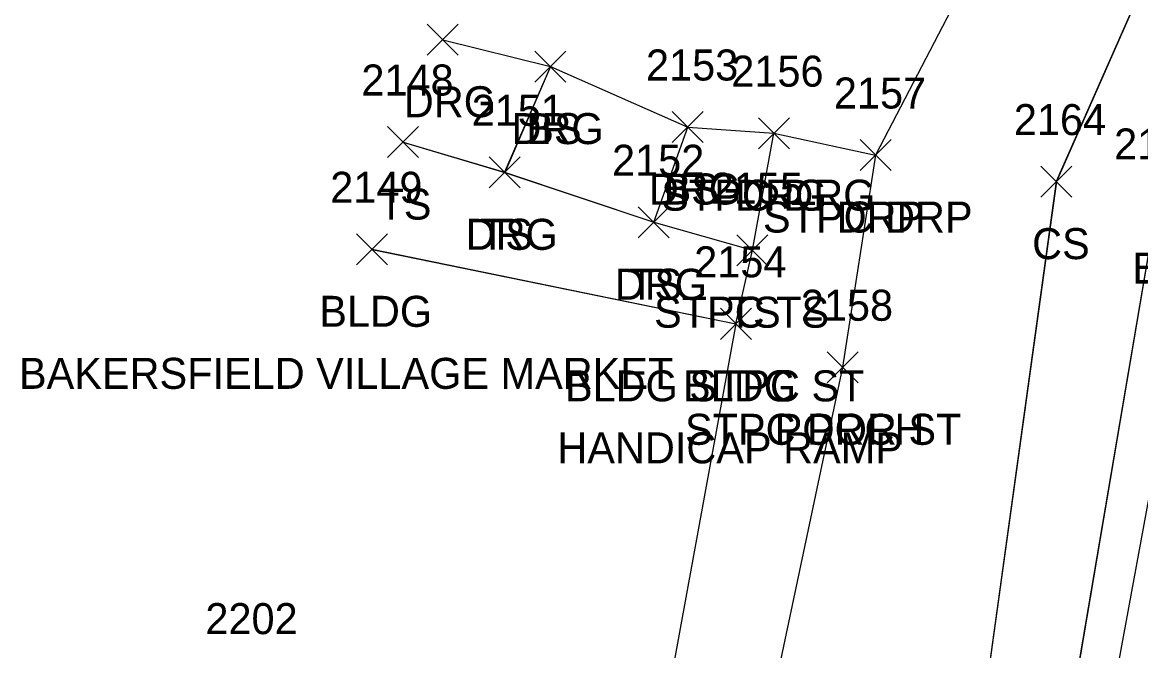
# Model space of a CAD drawing. Extents: x 1554668 to 1563881, y 831386 to 834374.
# Drawn here: x 1562076.1 to 1562148.2, y 832159.9 to 832200.4 of the extents above; entities that cross this region are included whole.
import ezdxf

# ---------------------------------------------------------------- set-up
doc = ezdxf.new("R2010")
doc.units = 0
for name, color, linetype in [('L_A', 7, 'Continuous'), ('L_C', 7, 'Continuous'), ('L_I', 7, 'Continuous'), ('L_TIC', 7, 'Continuous'), ('LBC', 7, 'Continuous'), ('LBF', 7, 'Continuous'), ('LELB', 7, 'Continuous'), ('PET', 7, 'Continuous'), ('R_A', 7, 'Continuous'), ('R_I', 7, 'Continuous'), ('R_TIC', 7, 'Continuous'), ('RDG', 7, 'Continuous'), ('RDP', 7, 'Continuous')]:
    doc.layers.add(name, color=color, linetype=linetype)

msp = doc.modelspace()

# ---------------------------------------------------------------- linework, layer by layer
at = {"layer": 'L_TIC'}
for points in [[(1562109.153, 832196.571), (1562111.153, 832198.571)], [(1562111.153, 832196.571), (1562109.153, 832198.571)], [(1562118.011, 832192.673), (1562120.011, 832194.673)], [(1562120.011, 832192.673), (1562118.011, 832194.673)], [(1562123.569, 832192.276), (1562125.569, 832194.276)], [(1562125.569, 832192.276), (1562123.569, 832194.276)], [(1562099.654, 832191.705), (1562101.654, 832193.705)], [(1562101.654, 832191.705), (1562099.654, 832193.705)], [(1562130.13, 832190.866), (1562132.13, 832192.866)], [(1562132.13, 832190.866), (1562130.13, 832192.866)], [(1562106.199, 832189.752), (1562108.199, 832191.752)], [(1562108.199, 832189.752), (1562106.199, 832191.752)], [(1562141.785, 832189.152), (1562143.785, 832191.152)], [(1562143.785, 832189.152), (1562141.785, 832191.152)], [(1562115.821, 832186.53), (1562117.821, 832188.53)], [(1562117.821, 832186.53), (1562115.821, 832188.53)], [(1562097.651, 832184.786), (1562099.651, 832186.786)], [(1562099.651, 832184.786), (1562097.651, 832186.786)], [(1562122.185, 832184.729), (1562124.185, 832186.729)], [(1562124.185, 832184.729), (1562122.185, 832186.729)], [(1562122.185, 832184.729), (1562124.185, 832186.729)], [(1562124.185, 832184.729), (1562122.185, 832186.729)], [(1562121.12, 832179.979), (1562123.12, 832181.979)], [(1562123.12, 832179.979), (1562121.12, 832181.979)], [(1562121.12, 832179.979), (1562123.12, 832181.979)], [(1562123.12, 832179.979), (1562121.12, 832181.979)], [(1562127.997, 832177.178), (1562129.997, 832179.178)], [(1562129.997, 832177.178), (1562127.997, 832179.178)], [(1562127.997, 832177.178), (1562129.997, 832179.178)], [(1562129.997, 832177.178), (1562127.997, 832179.178)]]:
    msp.add_lwpolyline(points, dxfattribs=at)
at = {"layer": 'LBC'}
for points in [[(1562098.651, 832185.786), (1562122.12, 832180.979), (1562116.884, 832152.384), (1562091.236, 832157.966)], [(1562098.652, 832185.784), (1562122.122, 832180.976)], [(1562098.652, 832185.784), (1562122.122, 832180.976)], [(1562098.652, 832185.784), (1562122.122, 832180.976)]]:
    msp.add_lwpolyline(points, dxfattribs=at)
at = {"layer": 'LBF'}
for points in [[(1562122.12, 832180.979), (1562123.185, 832185.729), (1562124.569, 832193.276), (1562131.13, 832191.866), (1562128.997, 832178.178)], [(1562122.122, 832180.976), (1562123.192, 832185.728), (1562124.571, 832193.274), (1562131.131, 832191.864), (1562129.002, 832178.176)], [(1562122.122, 832180.976), (1562123.192, 832185.728), (1562124.571, 832193.274), (1562131.131, 832191.864), (1562129.002, 832178.176)], [(1562122.122, 832180.976), (1562123.192, 832185.728), (1562124.571, 832193.274), (1562131.131, 832191.864), (1562129.002, 832178.176)], [(1562128.997, 832178.178), (1562123.536, 832152.362)], [(1562129.002, 832178.176), (1562123.54, 832152.361)], [(1562129.002, 832178.176), (1562123.54, 832152.361)], [(1562129.002, 832178.176), (1562123.54, 832152.361)]]:
    msp.add_lwpolyline(points, dxfattribs=at)
at = {"layer": 'LELB'}
for points in [[(1562159.554, 832227.311), (1562154.233, 832216.107), (1562149.254, 832188.579), (1562142.829, 832150.769), (1562138.278, 832124.139), (1562134.77, 832104.225), (1562125.205, 832097.127)], [(1562159.553, 832227.312), (1562154.234, 832216.106), (1562149.258, 832188.577), (1562142.835, 832150.769), (1562138.281, 832124.137), (1562134.773, 832104.223), (1562125.206, 832097.122)], [(1562159.553, 832227.312), (1562154.234, 832216.106), (1562149.258, 832188.577), (1562142.835, 832150.769), (1562138.281, 832124.137), (1562134.773, 832104.223), (1562125.206, 832097.122)], [(1562159.553, 832227.312), (1562154.234, 832216.106), (1562149.258, 832188.577), (1562142.835, 832150.769), (1562138.281, 832124.137), (1562134.773, 832104.223), (1562125.206, 832097.122)], [(1562154.233, 832216.107), (1562142.785, 832190.152), (1562137.399, 832151.265), (1562131.854, 832132.751)], [(1562154.234, 832216.106), (1562142.793, 832190.15), (1562137.4, 832151.262), (1562131.857, 832132.749)], [(1562154.234, 832216.106), (1562142.793, 832190.15), (1562137.4, 832151.262), (1562131.857, 832132.749)], [(1562154.234, 832216.106), (1562142.793, 832190.15), (1562137.4, 832151.262), (1562131.857, 832132.749)], [(1562110.153, 832197.571), (1562119.011, 832193.673)], [(1562110.161, 832197.569), (1562119.011, 832193.671)], [(1562110.161, 832197.569), (1562119.011, 832193.671)], [(1562110.161, 832197.569), (1562119.011, 832193.671)], [(1562100.654, 832192.705), (1562107.199, 832190.752)], [(1562100.656, 832192.702), (1562107.204, 832190.75)], [(1562100.656, 832192.702), (1562107.204, 832190.75)], [(1562100.656, 832192.702), (1562107.204, 832190.75)], [(1562116.821, 832187.53), (1562123.185, 832185.729)], [(1562116.823, 832187.528), (1562123.192, 832185.728)], [(1562116.823, 832187.528), (1562123.192, 832185.728)], [(1562116.823, 832187.528), (1562123.192, 832185.728)]]:
    msp.add_lwpolyline(points, dxfattribs=at)
at = {"layer": 'PET'}
for points in [[(1562173.257, 832299.981), (1562167.837, 832271.725), (1562161.659, 832238.665), (1562161.437, 832236.524), (1562159.553, 832227.312), (1562152.096, 832187.901), (1562145.122, 832150.033), (1562139.531, 832121.079), (1562137.129, 832105.561), (1562131.774, 832078.931), (1562126.825, 832053.768), (1562119.399, 832015.882), (1562118.509, 832011.052), (1562111.401, 831974.91), (1562102.865, 831928.04), (1562098.612, 831906.222)], [(1562173.257, 832299.981), (1562167.837, 832271.725), (1562161.659, 832238.665), (1562161.437, 832236.524), (1562159.553, 832227.312), (1562152.096, 832187.901), (1562145.122, 832150.033), (1562139.531, 832121.079), (1562137.129, 832105.561), (1562131.774, 832078.931), (1562126.825, 832053.768), (1562119.399, 832015.882), (1562118.509, 832011.052), (1562111.401, 831974.91), (1562102.865, 831928.04), (1562098.612, 831906.222)], [(1562173.257, 832299.981), (1562167.837, 832271.725), (1562161.659, 832238.665), (1562161.437, 832236.524), (1562159.553, 832227.312), (1562152.096, 832187.901), (1562145.122, 832150.033), (1562139.531, 832121.079), (1562137.129, 832105.561), (1562131.774, 832078.931), (1562126.825, 832053.768), (1562119.399, 832015.882), (1562118.509, 832011.052), (1562111.401, 831974.91), (1562102.865, 831928.04), (1562098.612, 831906.222)], [(1562173.255, 832299.979), (1562167.833, 832271.729), (1562161.658, 832238.665), (1562161.431, 832236.528), (1562159.554, 832227.311), (1562152.09, 832187.903), (1562145.121, 832150.036), (1562139.525, 832121.078), (1562137.127, 832105.565), (1562131.768, 832078.929), (1562126.821, 832053.77), (1562119.402, 832015.881), (1562118.513, 832011.051), (1562111.4, 831974.907), (1562102.869, 831928.042), (1562098.613, 831906.218)]]:
    msp.add_lwpolyline(points, dxfattribs=at)
at = {"layer": 'R_TIC'}
for points in [[(1562102.209, 832198.302), (1562104.209, 832200.302)], [(1562104.209, 832198.302), (1562102.209, 832200.302)], [(1562109.153, 832196.571), (1562111.153, 832198.571)], [(1562111.153, 832196.571), (1562109.153, 832198.571)], [(1562118.011, 832192.673), (1562120.011, 832194.673)], [(1562120.011, 832192.673), (1562118.011, 832194.673)], [(1562123.569, 832192.276), (1562125.569, 832194.276)], [(1562125.569, 832192.276), (1562123.569, 832194.276)], [(1562130.13, 832190.866), (1562132.13, 832192.866)], [(1562132.13, 832190.866), (1562130.13, 832192.866)], [(1562106.199, 832189.752), (1562108.199, 832191.752)], [(1562108.199, 832189.752), (1562106.199, 832191.752)], [(1562115.821, 832186.53), (1562117.821, 832188.53)], [(1562117.821, 832186.53), (1562115.821, 832188.53)]]:
    msp.add_lwpolyline(points, dxfattribs=at)
at = {"layer": 'RDG'}
for points in [[(1562103.209, 832199.302), (1562110.153, 832197.571), (1562107.199, 832190.752), (1562116.821, 832187.53), (1562119.011, 832193.673), (1562124.569, 832193.276)], [(1562103.217, 832199.299), (1562110.161, 832197.569), (1562107.204, 832190.75), (1562116.823, 832187.528), (1562119.011, 832193.671), (1562124.571, 832193.274)], [(1562103.217, 832199.299), (1562110.161, 832197.569), (1562107.204, 832190.75), (1562116.823, 832187.528), (1562119.011, 832193.671), (1562124.571, 832193.274)], [(1562103.217, 832199.299), (1562110.161, 832197.569), (1562107.204, 832190.75), (1562116.823, 832187.528), (1562119.011, 832193.671), (1562124.571, 832193.274)]]:
    msp.add_lwpolyline(points, dxfattribs=at)
at = {"layer": 'RDP'}
for points in [[(1562161.431, 832236.528), (1562154.47, 832237.873), (1562151.444, 832238.981), (1562143.186, 832225.343), (1562143.005, 832214.706), (1562131.13, 832191.866)], [(1562161.437, 832236.524), (1562154.471, 832237.873), (1562151.45, 832238.977), (1562143.191, 832225.34), (1562143.012, 832214.704), (1562131.131, 832191.864)], [(1562161.437, 832236.524), (1562154.471, 832237.873), (1562151.45, 832238.977), (1562143.191, 832225.34), (1562143.012, 832214.704), (1562131.131, 832191.864)], [(1562161.437, 832236.524), (1562154.471, 832237.873), (1562151.45, 832238.977), (1562143.191, 832225.34), (1562143.012, 832214.704), (1562131.131, 832191.864)]]:
    msp.add_lwpolyline(points, dxfattribs=at)

# ---------------------------------------------------------------- texts
at = {"layer": 'L_A'}
for s, p in [('BS', (1562108.594, 832192.571)), ('BS', (1562117.452, 832188.673)), ('TS', (1562099.063, 832187.705)), ('STPC DRG', (1562117.301, 832188.276)), ('STPC DRP', (1562123.862, 832186.866)), ('TS', (1562105.608, 832185.752)), ('CS', (1562141.226, 832185.152)), ('BS', (1562147.695, 832183.579)), ('TS', (1562115.23, 832182.53)), ('BLDG', (1562095.241, 832180.786)), ('STPC TS', (1562116.838, 832180.729)), ('TS', (1562121.594, 832180.729)), ('BLDG STPC ST', (1562111.089, 832175.979)), ('BLDG', (1562118.711, 832175.979)), ('STPC POR ST', (1562118.831, 832173.178)), ('PORCH', (1562124.619, 832173.178))]:
    msp.add_text(s, height=2, dxfattribs=at).set_placement(p)
at = {"layer": 'L_C'}
for s, p in [('BAKERSFIELD VILLAGE MARKET', (1562075.871, 832176.786)), ('HANDICAP RAMP', (1562110.6, 832171.979))]:
    msp.add_text(s, height=2, dxfattribs=at).set_placement(p)
at = {"layer": 'L_I'}
for s, p in [('2153', (1562116.318, 832196.673)), ('2148', (1562097.961, 832195.705)), ('2156', (1562121.821, 832196.276)), ('2157', (1562128.437, 832194.866)), ('2151', (1562105.073, 832193.752)), ('2164', (1562140.045, 832193.152)), ('2165', (1562146.514, 832191.579)), ('2152', (1562114.128, 832190.53)), ('2149', (1562095.95, 832188.786)), ('2155', (1562120.492, 832188.729)), ('2155', (1562120.492, 832188.729)), ('2154', (1562119.427, 832183.979)), ('2154', (1562119.427, 832183.979)), ('2158', (1562126.304, 832181.178)), ('2158', (1562126.304, 832181.178)), ('2202', (1562087.897, 832160.966))]:
    msp.add_text(s, height=2, dxfattribs=at).set_placement(p)
at = {"layer": 'R_A'}
for s, p in [('DRG', (1562100.698, 832194.302)), ('DRG', (1562107.641, 832192.571)), ('DRG', (1562116.499, 832188.673)), ('DRG', (1562122.057, 832188.276)), ('DRP', (1562128.618, 832186.866)), ('DRG', (1562104.687, 832185.752)), ('DRG', (1562114.309, 832182.53))]:
    msp.add_text(s, height=2, dxfattribs=at).set_placement(p)
at = {"layer": 'R_I'}
for s, p in [('2153', (1562116.318, 832196.673)), ('2156', (1562121.821, 832196.276)), ('2157', (1562128.437, 832194.866)), ('2151', (1562105.073, 832193.752)), ('2152', (1562114.128, 832190.53))]:
    msp.add_text(s, height=2, dxfattribs=at).set_placement(p)

doc.saveas('drawing.dxf')
